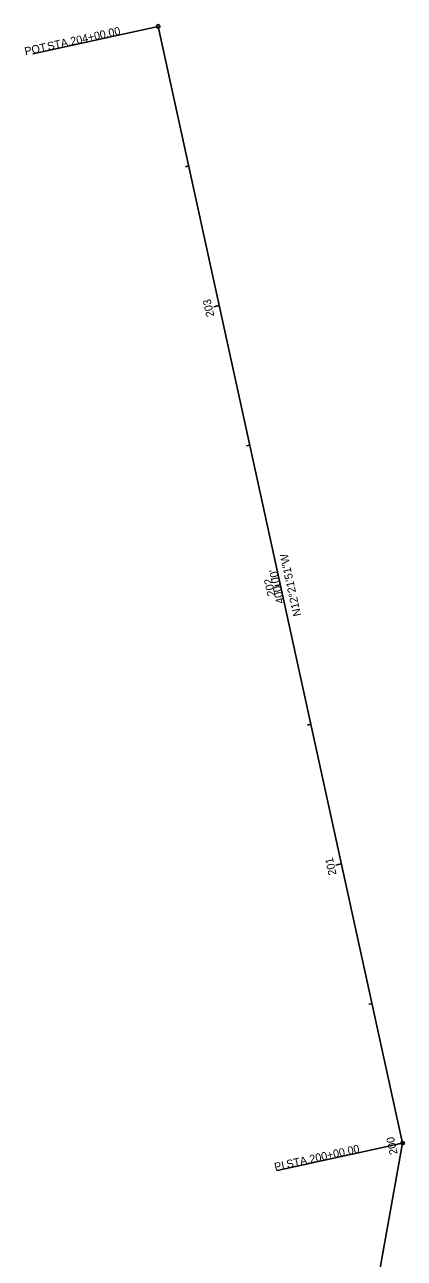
# Model space of a CAD drawing. Extents: x 216512 to 216645, y 458360 to 459225.
# Drawn here: x 216512 to 216645.1, y 458793.3 to 459224.9 of the extents above; entities that cross this region are included whole.
import ezdxf

# ---------------------------------------------------------------- set-up
doc = ezdxf.new("R2010")
doc.units = 0
for name, color, linetype in [('RW_X_CL', 7, 'Continuous'), ('RW_X_CL_100_Bearings', 7, 'Continuous'), ('RW_X_CL_100_Cardinal_Points', 7, 'Continuous'), ('RW_X_CL_100_Distances', 7, 'Continuous'), ('RW_X_CL_100_Stations', 7, 'Continuous'), ('RW_X_CL_500_Bearings', 7, 'Continuous'), ('RW_X_CL_500_Cardinal_Points', 7, 'Continuous'), ('RW_X_CL_500_Distances', 7, 'Continuous'), ('RW_X_CL_500_Stations', 7, 'Continuous')]:
    doc.layers.add(name, color=color, linetype=linetype)

msp = doc.modelspace()

# ---------------------------------------------------------------- linework, layer by layer
at = {"layer": 'RW_X_CL'}
for p, q in [((216644.48, 458833.6), (216558.83, 459224.33)), ((216558.59, 458360.2), (216644.48, 458833.6))]:
    msp.add_line(p, q, dxfattribs=at)
at = {"layer": 'RW_X_CL_100_Cardinal_Points'}
for p, q in [((216558.83, 459224.33), (216514.88, 459214.69)), ((216644.48, 458833.6), (216600.53, 458823.97))]:
    msp.add_line(p, q, dxfattribs=at)
for centre in [(216558.83, 459224.33), (216644.48, 458833.6)]:
    msp.add_circle(centre, 0.6, dxfattribs=at)
at = {"layer": 'RW_X_CL_100_Stations'}
for p, q in [((216569.54, 459175.49), (216568.37, 459175.23)), ((216580.25, 459126.64), (216578.29, 459126.22)), ((216590.95, 459077.8), (216589.78, 459077.55)), ((216601.66, 459028.96), (216599.7, 459028.54)), ((216612.36, 458980.12), (216611.19, 458979.87)), ((216623.07, 458931.28), (216621.12, 458930.86)), ((216633.78, 458882.44), (216632.6, 458882.19)), ((216644.48, 458833.6), (216642.53, 458833.17))]:
    msp.add_line(p, q, dxfattribs=at)
at = {"layer": 'RW_X_CL_500_Cardinal_Points'}
for p, q in [((216558.83, 459224.33), (216514.88, 459214.69)), ((216644.48, 458833.6), (216600.53, 458823.97))]:
    msp.add_line(p, q, dxfattribs=at)
for centre in [(216558.83, 459224.33), (216644.48, 458833.6)]:
    msp.add_circle(centre, 0.6, dxfattribs=at)
at = {"layer": 'RW_X_CL_500_Stations'}
for p, q in [((216580.25, 459126.64), (216579.07, 459126.39)), ((216601.66, 459028.96), (216600.49, 459028.71)), ((216623.07, 458931.28), (216621.9, 458931.03)), ((216644.48, 458833.6), (216642.53, 458833.17))]:
    msp.add_line(p, q, dxfattribs=at)

# ---------------------------------------------------------------- texts
at = {"layer": 'RW_X_CL_100_Bearings'}
msp.add_text('N12°21\'51"W', height=2.8, rotation=102.3641, dxfattribs=at).set_placement((216608.92, 459018.24))
at = {"layer": 'RW_X_CL_100_Cardinal_Points'}
for s, p in [('204+00.00', (216528.4, 459217.69)), ('POT', (216512.33, 459214.17)), (' STA. ', (216519.29, 459215.7)), ('200+00.00', (216612.19, 458826.56)), (' STA. ', (216603.08, 458824.56)), ('PI', (216599.84, 458823.85))]:
    msp.add_text(s, height=2.8, rotation=12.3641, dxfattribs=at).set_placement(p)
at = {"layer": 'RW_X_CL_100_Distances'}
msp.add_text("400.00'", height=2.8, rotation=102.3641, dxfattribs=at).set_placement((216603, 459022.67))
at = {"layer": 'RW_X_CL_100_Stations'}
for s, p in [('203', (216578.49, 459122.99)), ('202', (216599.9, 459025.29)), ('201', (216621.32, 458927.6)), ('200', (216642.74, 458829.88))]:
    msp.add_text(s, height=2.8, rotation=102.3641, dxfattribs=at).set_placement(p)
at = {"layer": 'RW_X_CL_500_Bearings'}
msp.add_text('N12°21\'51"W', height=2.8, rotation=102.3641, dxfattribs=at).set_placement((216608.92, 459018.24))
at = {"layer": 'RW_X_CL_500_Cardinal_Points'}
for s, p in [('204+00.00', (216528.4, 459217.69)), ('POT', (216512.33, 459214.17)), (' STA. ', (216519.29, 459215.7)), ('200+00.00', (216612.19, 458826.56)), (' STA. ', (216603.08, 458824.56)), ('PI', (216599.84, 458823.85))]:
    msp.add_text(s, height=2.8, rotation=12.3641, dxfattribs=at).set_placement(p)
at = {"layer": 'RW_X_CL_500_Distances'}
msp.add_text("400.00'", height=2.8, rotation=102.3641, dxfattribs=at).set_placement((216603, 459022.67))
at = {"layer": 'RW_X_CL_500_Stations'}
msp.add_text('200', height=2.8, rotation=102.3641, dxfattribs=at).set_placement((216642.74, 458829.88))

doc.saveas('drawing.dxf')
